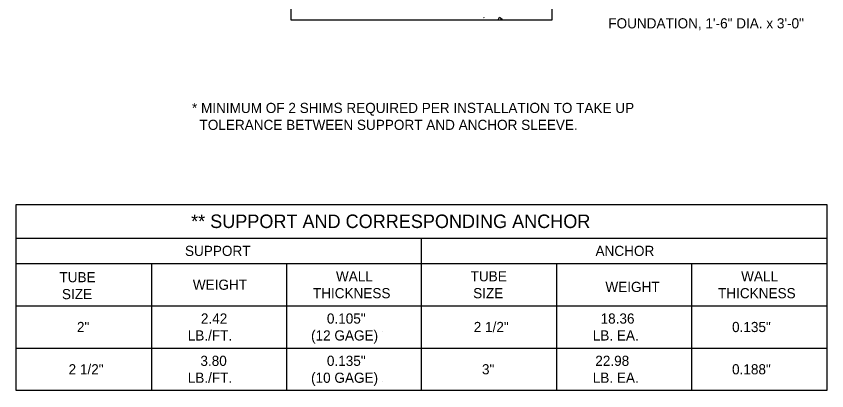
# Model space of a CAD drawing. Extents: x 49940 to 50043, y 49986 to 50011.
# Drawn here: x 49961.92 to 49966.717, y 49990.377 to 49992.591 of the extents above; entities that cross this region are included whole.
import ezdxf

# ---------------------------------------------------------------- set-up
doc = ezdxf.new("R2010")
doc.units = 0
doc.layers.add('Level 1', color=7, linetype='Continuous')
doc.layers.add('Level 2', color=7, linetype='Continuous')

msp = doc.modelspace()

# ---------------------------------------------------------------- linework, layer by layer
at = {"layer": 'Level 1'}
for p, q in [((49963.5456, 49995.2967), (49963.5456, 49992.5705)), ((49965.0906, 49992.5705), (49965.0906, 49995.2967)), ((49964.6846, 49992.5862), (49964.6877, 49992.5813)), ((49963.5456, 49992.5705), (49965.0906, 49992.5705))]:
    msp.add_line(p, q, dxfattribs=at)
msp.add_lwpolyline([(49964.7717, 49992.5705), (49964.7789, 49992.5855), (49964.7951, 49992.5734), (49964.786, 49992.5705)], dxfattribs=at)
at = {"layer": 'Level 2'}
for p, q in [((49961.9197, 49991.4787), (49966.7166, 49991.4787)), ((49961.9197, 49990.3787), (49961.9197, 49991.4787)), ((49966.7166, 49991.4787), (49966.7166, 49990.3787)), ((49961.9197, 49991.2787), (49966.7166, 49991.2787)), ((49964.3166, 49991.2787), (49964.3166, 49990.3787)), ((49961.9197, 49991.1287), (49966.7166, 49991.1287)), ((49962.7197, 49991.1287), (49962.7197, 49990.3787)), ((49962.7197, 49991.1287), (49962.7197, 49991.1287)), ((49963.5197, 49991.1287), (49963.5197, 49990.3787)), ((49964.3166, 49991.1287), (49964.3166, 49991.1287)), ((49965.1166, 49991.1287), (49965.1166, 49990.3766)), ((49965.9166, 49991.1287), (49965.9166, 49990.3787)), ((49961.9197, 49990.8787), (49966.7166, 49990.8787)), ((49962.7197, 49990.8787), (49962.7197, 49990.8787)), ((49963.5197, 49990.8787), (49963.5197, 49990.8787)), ((49964.3166, 49990.8787), (49964.3166, 49990.8787)), ((49965.1166, 49990.8787), (49965.1166, 49990.8787)), ((49965.9166, 49990.8787), (49965.9166, 49990.8787)), ((49964.0886, 49990.7285), (49964.0886, 49990.7285)), ((49961.9197, 49990.6287), (49966.7166, 49990.6287)), ((49962.7197, 49990.6287), (49962.7197, 49990.6287)), ((49963.5197, 49990.6287), (49963.5197, 49990.6287)), ((49964.3166, 49990.6287), (49964.3166, 49990.6287)), ((49965.1166, 49990.6287), (49965.1166, 49990.6287)), ((49965.9166, 49990.6287), (49965.9166, 49990.6287)), ((49964.0886, 49990.429), (49964.0886, 49990.429)), ((49966.7166, 49990.3787), (49961.9197, 49990.3787))]:
    msp.add_line(p, q, dxfattribs=at)

# ---------------------------------------------------------------- texts
for s, height, p in [('FOUNDATION, 1\'-6" DIA. x 3\'-0"', 0.06, (49965.4236, 49992.519)), ('* MINIMUM OF 2 SHIMS REQUIRED PER INSTALLATION TO TAKE UP   ', 0.06, (49962.9599, 49992.0188)), ('  TOLERANCE BETWEEN SUPPORT AND ANCHOR SLEEVE.', 0.06, (49962.9599, 49991.9188)), ('** SUPPORT AND CORRESPONDING ANCHOR', 0.0799, (49962.9548, 49991.3387)), ('SUPPORT', 0.06, (49962.9185, 49991.1737)), ('ANCHOR', 0.06, (49965.348, 49991.1737)), ('TUBE', 0.06, (49962.1755, 49991.0182)), ('WALL', 0.06, (49963.8119, 49991.0237)), ('TUBE', 0.06, (49964.6089, 49991.0237)), ('WALL', 0.06, (49966.2096, 49991.0237)), ('WEIGHT', 0.06, (49962.965, 49990.9737)), ('WEIGHT', 0.06, (49965.4066, 49990.9607)), ('SIZE', 0.06, (49962.1904, 49990.9182)), ('THICKNESS', 0.06, (49963.6754, 49990.9237)), ('SIZE', 0.06, (49964.6238, 49990.9237)), ('THICKNESS', 0.06, (49966.0731, 49990.9237)), ('2.42', 0.06, (49963.0127, 49990.7737)), ('0.105"', 0.06, (49963.7583, 49990.7737)), ('18.36', 0.06, (49965.378, 49990.7737)), ('2"', 0.06, (49962.2791, 49990.7237)), ('2 1/2"', 0.06, (49964.6273, 49990.7237)), ('0.135"', 0.06, (49966.156, 49990.7237)), ('LB./FT.', 0.06, (49962.9349, 49990.6737)), ('(12 GAGE)', 0.06, (49963.6645, 49990.6737)), ('LB. EA.', 0.06, (49965.3318, 49990.6737)), ('3.80', 0.06, (49963.0097, 49990.5237)), ('0.135"', 0.06, (49963.7583, 49990.5237)), ('22.98 ', 0.06, (49965.3466, 49990.5237)), ('2 1/2"', 0.06, (49962.2297, 49990.4737)), ('3"', 0.06, (49964.676, 49990.4737)), ('0.188"', 0.06, (49966.156, 49990.4737)), ('LB./FT.', 0.06, (49962.9349, 49990.4237)), ('(10 GAGE)', 0.06, (49963.6645, 49990.4237)), ('LB. EA.', 0.06, (49965.3318, 49990.4237))]:
    msp.add_text(s, height=height, dxfattribs=at).set_placement(p)

doc.saveas('drawing.dxf')
